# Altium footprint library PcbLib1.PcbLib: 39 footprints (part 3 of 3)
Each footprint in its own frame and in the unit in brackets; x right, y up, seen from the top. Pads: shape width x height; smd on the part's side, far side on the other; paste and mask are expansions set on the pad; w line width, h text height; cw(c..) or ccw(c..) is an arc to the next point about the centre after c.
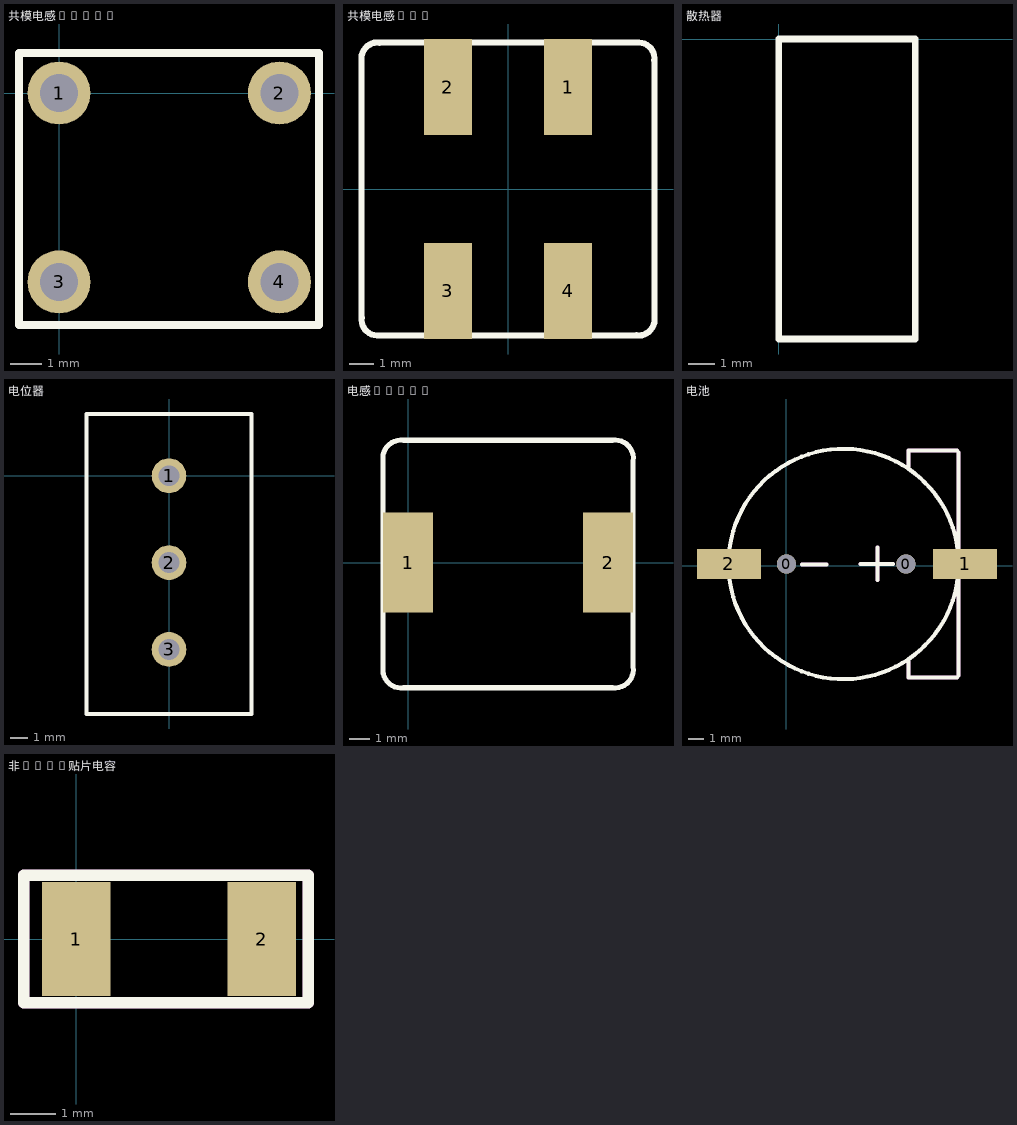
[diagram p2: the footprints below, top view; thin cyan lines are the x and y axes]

## 共模电感150uH [mm]
pads (4):
  round 2 hole 1.2: 1(0,0) 2(7,0) 3(0,-6) 4(7,-6)
Top Overlay:
  lines w0.254: -1.27,-7.366 -1.27,1.27 8.255,1.27 8.255,-7.366 -1.27,-7.366

## 共模电感154 [mm]
pads (4):
  rect 2x4 smd: 1(2.5,4.25) 2(-2.5,4.25) 3(-2.5,-4.25) 4(2.5,-4.25)
Top Overlay:
  lines w0.254: -6.1,-5.457 -6.1,5.584 ; -6.087,-5.357 ccw(c-5.461,-5.461) -5.581,-6.085 ; -6.085,5.581 cw(c-5.461,5.461) -5.357,6.087 ; -5.584,6.1 -5.298,6.1 -5.294,6.096 5.461,6.096 ; -5.457,-6.1 5.584,-6.1 ; 5.357,-6.087 ccw(c5.461,-5.461) 6.085,-5.581 ; 5.581,6.085 cw(c5.461,5.461) 6.087,5.357 ; 6.1,-5.584 6.1,5.457

## 散热器 [mm]
Top Overlay:
  lines w0.254: 0,-11.176 5.08,-11.176 5.08,0 0,0 0,-11.176

## 电位器 [mm]
pads (3):
  round 2 hole 1.2: 1(0,0) 2(0,-5) 3(0,-10)
Top Overlay:
  lines w0.254: -4.75,3.5 -4.75,-13.5 -4.75,-13.716 4.75,-13.716 4.75,3.556 -4.75,3.556

## 电感12*12 [mm]
pads (2):
  rect 2.5x5 smd: 1(0,0) 2(10,0)
Top Overlay:
  lines w0.254: -1.25,-5.39 -1.25,5.088 cw(c-0.343,5.218) -0.224,6.126 10.22,6.126 cw(c10.35,5.219) 11.258,5.1 11.258,-5.215 cw(c10.351,-5.345) 10.232,-6.253 -0.212,-6.253 cw(c-0.342,-5.346) -1.25,-5.227

## 电池 [mm]
pads (4):
  round 1.2 hole 1.2: 0(0.009,0.113) 0(7.502,0.113)
  rect 4x1.9 smd: 1(11.21,0.113) 2(-3.597,0.113)
Top Overlay:
  circle w0.254: c3.59,0.113 r7.22
Top Overlay keep-out:
  lines w0.254: 0.993,0.069 2.517,0.069 ; 4.651,0.12 6.683,0.12 ; 5.718,-0.896 5.718,1.136 ; 7.654,-5.983 7.654,-6.999 10.702,-6.999 10.81,-6.89 10.81,0.113 10.81,7.117 10.702,7.225 7.654,7.225 7.654,6.209

## 非0805贴片电容 [mm]
pads (2):
  rect 1.5x2.5 smd: 1(0,0) 2(4.064,0)
Top Overlay keep-out:
  lines w0.254: -1.143,-1.397 -1.143,1.397 5.08,1.397 5.08,-1.397 -1.143,-1.397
